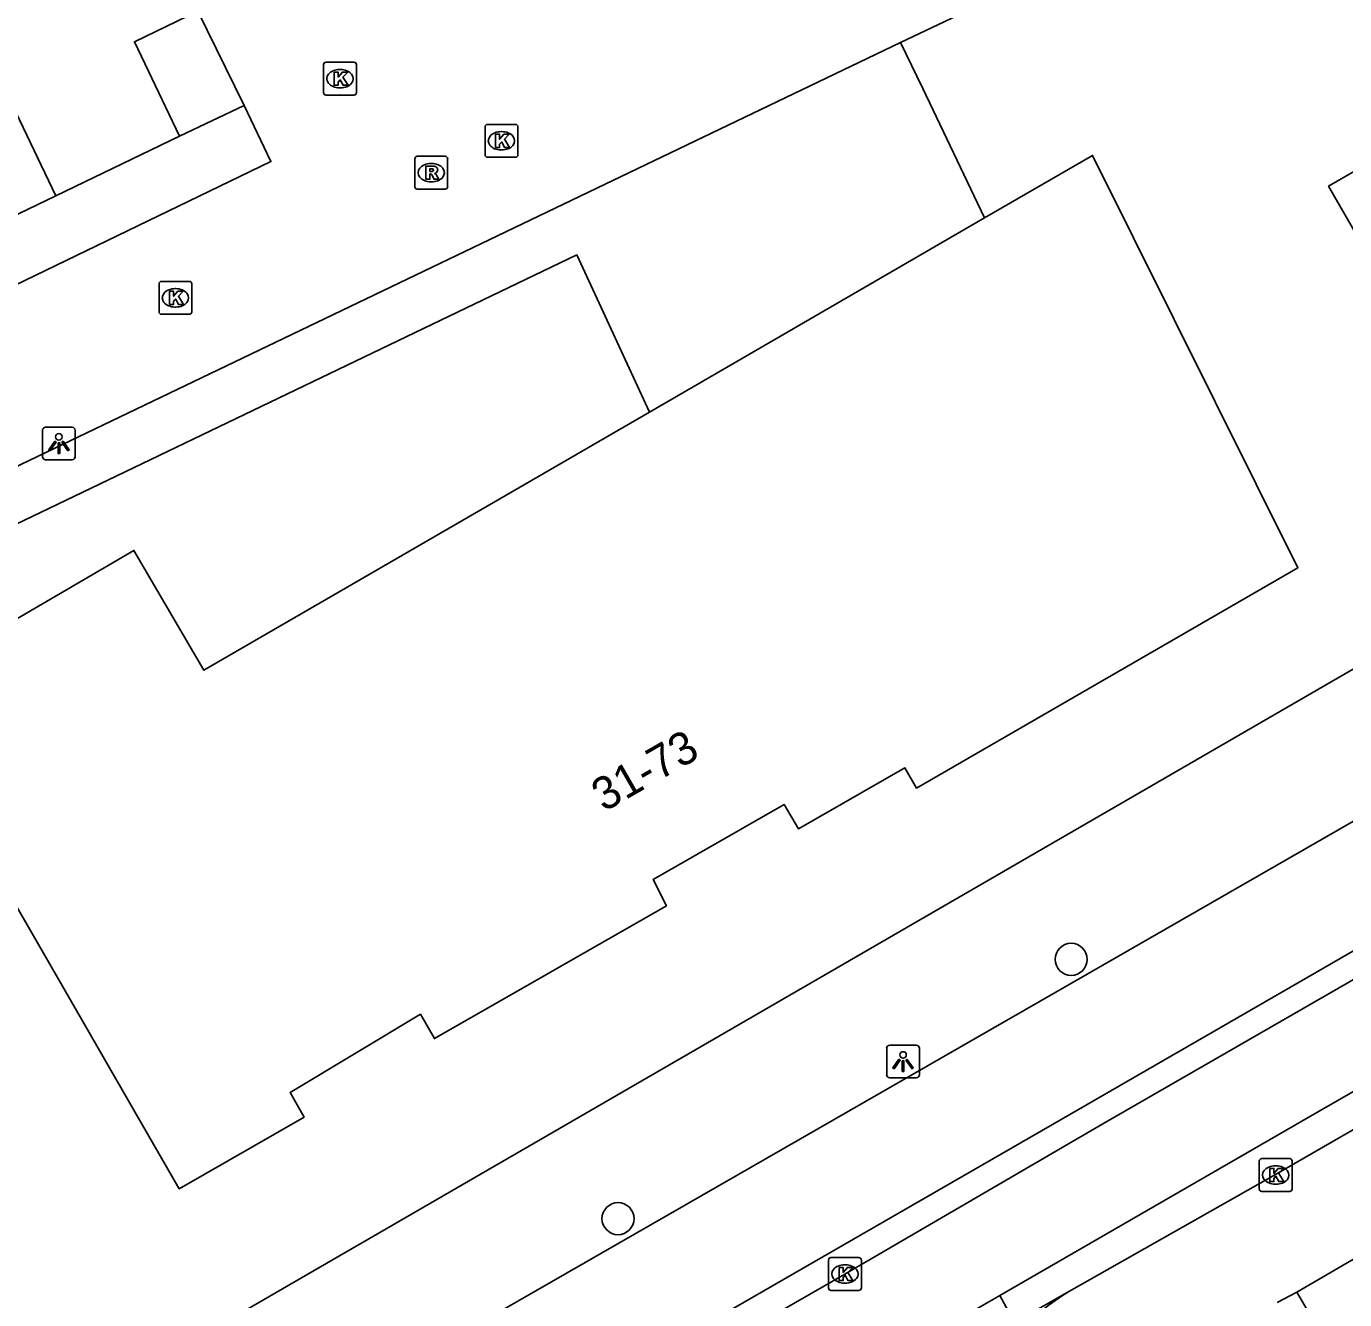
# Model space of a CAD drawing. Extents: x 158352 to 159489, y 383828 to 384597.
# Drawn here: x 159132.68 to 159172.84, y 383975.15 to 384013.95 of the extents above; entities that cross this region are included whole.
import ezdxf

# ---------------------------------------------------------------- set-up
doc = ezdxf.new("R2010")
doc.units = 0
for name, color, linetype in [('IMGEO_Boom', 7, 'Continuous'), ('IMGEO_Fietspad_gesloten', 7, 'Continuous'), ('IMGEO_Haag', 7, 'Continuous'), ('IMGEO_Kolk', 7, 'Continuous'), ('IMGEO_Lichtpunt', 7, 'Continuous'), ('IMGEO_Muur', 7, 'Continuous'), ('IMGEO_Pand', 7, 'Continuous'), ('IMGEO_Pand_nummerreeks', 7, 'Continuous'), ('IMGEO_Rijbaan_lokaal_open', 7, 'Continuous'), ('IMGEO_Rioolput', 7, 'Continuous'), ('IMGEO_Voetpad_open', 7, 'Continuous')]:
    doc.layers.add(name, color=color, linetype=linetype)

msp = doc.modelspace()

# ---------------------------------------------------------------- linework, layer by layer
at = {"layer": 'IMGEO_Boom'}
for centre in [(159164.512, 383985.52), (159150.704, 383977.62)]:
    msp.add_circle(centre, 0.489, dxfattribs=at)
at = {"layer": 'IMGEO_Fietspad_gesloten'}
for points in [[(159135.007, 383967.844), (159157.291, 383980.642), (159178.438, 383992.79)], [(159183.59, 383991.819), (159163.947, 383980.489), (159139.352, 383966.321)]]:
    msp.add_lwpolyline(points, dxfattribs=at)
at = {"layer": 'IMGEO_Haag'}
msp.add_lwpolyline([(159164.461, 383975.412), (159162.787, 383974.459), (159162.338, 383975.274)], dxfattribs=at)
at = {"layer": 'IMGEO_Kolk'}
for p, q in [((159141.732, 384011.926), (159141.732, 384012.778)), ((159141.807, 384012.852), (159142.659, 384012.852)), ((159142.22, 384012.632), (159142.245, 384012.632)), ((159142.733, 384012.778), (159142.733, 384011.926)), ((159142.659, 384011.852), (159141.807, 384011.852)), ((159142.243, 384012.072), (159142.218, 384012.072)), ((159146.652, 384010.034), (159146.652, 384010.886)), ((159146.727, 384010.96), (159147.579, 384010.96)), ((159147.653, 384010.886), (159147.653, 384010.034)), ((159147.14, 384010.74), (159147.165, 384010.74)), ((159147.163, 384010.18), (159147.138, 384010.18)), ((159147.579, 384009.96), (159146.727, 384009.96)), ((159136.718, 384005.249), (159136.718, 384006.101)), ((159136.793, 384006.175), (159137.645, 384006.175)), ((159137.719, 384006.101), (159137.719, 384005.249)), ((159137.206, 384005.955), (159137.231, 384005.955)), ((159137.229, 384005.395), (159137.204, 384005.395)), ((159137.645, 384005.175), (159136.793, 384005.175)), ((159170.243, 383978.523), (159170.243, 383979.375)), ((159170.318, 383979.449), (159171.17, 383979.449)), ((159170.731, 383979.229), (159170.756, 383979.229)), ((159171.244, 383979.375), (159171.244, 383978.523)), ((159171.17, 383978.449), (159170.318, 383978.449)), ((159170.754, 383978.669), (159170.729, 383978.669)), ((159157.118, 383975.508), (159157.118, 383976.36)), ((159157.193, 383976.434), (159158.045, 383976.434)), ((159158.119, 383976.36), (159158.119, 383975.508)), ((159157.606, 383976.214), (159157.631, 383976.214)), ((159157.629, 383975.654), (159157.604, 383975.654)), ((159158.045, 383975.434), (159157.193, 383975.434))]:
    msp.add_line(p, q, dxfattribs=at)
for points in [[(159141.732, 384011.926), (159141.732, 384012.778)], [(159141.807, 384012.852), (159142.659, 384012.852)], [(159142.053, 384012.552), (159142.176, 384012.552), (159142.176, 384012.401), (159142.306, 384012.552), (159142.47, 384012.552), (159142.324, 384012.401), (159142.477, 384012.152), (159142.325, 384012.152), (159142.24, 384012.316), (159142.176, 384012.249), (159142.176, 384012.152), (159142.053, 384012.152), (159142.053, 384012.552)], [(159142.733, 384012.778), (159142.733, 384011.926)], [(159142.659, 384011.852), (159141.807, 384011.852)], [(159146.652, 384010.034), (159146.652, 384010.886)], [(159146.727, 384010.96), (159147.579, 384010.96)], [(159147.653, 384010.886), (159147.653, 384010.034)], [(159146.973, 384010.66), (159147.096, 384010.66), (159147.096, 384010.509), (159147.226, 384010.66), (159147.39, 384010.66), (159147.244, 384010.509), (159147.397, 384010.26), (159147.245, 384010.26), (159147.16, 384010.424), (159147.096, 384010.357), (159147.096, 384010.26), (159146.973, 384010.26), (159146.973, 384010.66)], [(159147.579, 384009.96), (159146.727, 384009.96)], [(159136.718, 384005.249), (159136.718, 384006.101)], [(159136.793, 384006.175), (159137.645, 384006.175)], [(159137.719, 384006.101), (159137.719, 384005.249)], [(159137.039, 384005.875), (159137.162, 384005.875), (159137.162, 384005.724), (159137.292, 384005.875), (159137.456, 384005.875), (159137.31, 384005.724), (159137.463, 384005.475), (159137.311, 384005.475), (159137.226, 384005.639), (159137.162, 384005.572), (159137.162, 384005.475), (159137.039, 384005.475), (159137.039, 384005.875)], [(159137.645, 384005.175), (159136.793, 384005.175)], [(159170.243, 383978.523), (159170.243, 383979.375)], [(159170.318, 383979.449), (159171.17, 383979.449)], [(159171.244, 383979.375), (159171.244, 383978.523)], [(159170.564, 383979.149), (159170.687, 383979.149), (159170.687, 383978.998), (159170.817, 383979.149), (159170.981, 383979.149), (159170.835, 383978.998), (159170.988, 383978.749), (159170.836, 383978.749), (159170.751, 383978.913), (159170.687, 383978.846), (159170.687, 383978.749), (159170.564, 383978.749), (159170.564, 383979.149)], [(159171.17, 383978.449), (159170.318, 383978.449)], [(159157.118, 383975.508), (159157.118, 383976.36)], [(159157.193, 383976.434), (159158.045, 383976.434)], [(159158.119, 383976.36), (159158.119, 383975.508)], [(159157.439, 383976.134), (159157.562, 383976.134), (159157.562, 383975.983), (159157.692, 383976.134), (159157.856, 383976.134), (159157.71, 383975.983), (159157.863, 383975.734), (159157.711, 383975.734), (159157.626, 383975.898), (159157.562, 383975.831), (159157.562, 383975.734), (159157.439, 383975.734), (159157.439, 383976.134)], [(159158.045, 383975.434), (159157.193, 383975.434)]]:
    msp.add_lwpolyline(points, dxfattribs=at)
for centre, start, end in [((159141.809, 384012.776), 91.552, 178.448), ((159141.809, 384012.776), 91.552, 178.448), ((159142.657, 384012.776), 1.552, 88.448), ((159142.657, 384012.776), 1.552, 88.448), ((159141.809, 384011.928), 181.552, 268.448), ((159141.809, 384011.928), 181.552, 268.448), ((159142.657, 384011.928), 271.552, 358.448), ((159142.657, 384011.928), 271.552, 358.448), ((159146.729, 384010.884), 91.552, 178.448), ((159146.729, 384010.884), 91.552, 178.448), ((159147.577, 384010.884), 1.552, 88.448), ((159147.577, 384010.884), 1.552, 88.448), ((159146.729, 384010.036), 181.552, 268.448), ((159146.729, 384010.036), 181.552, 268.448), ((159147.577, 384010.036), 271.552, 358.448), ((159147.577, 384010.036), 271.552, 358.448), ((159136.795, 384006.099), 91.552, 178.448), ((159136.795, 384006.099), 91.552, 178.448), ((159137.643, 384006.099), 1.552, 88.448), ((159137.643, 384006.099), 1.552, 88.448), ((159136.795, 384005.251), 181.552, 268.448), ((159136.795, 384005.251), 181.552, 268.448), ((159137.643, 384005.251), 271.552, 358.448), ((159137.643, 384005.251), 271.552, 358.448), ((159170.32, 383979.373), 91.552, 178.448), ((159170.32, 383979.373), 91.552, 178.448), ((159171.168, 383979.373), 1.552, 88.448), ((159171.168, 383979.373), 1.552, 88.448), ((159170.32, 383978.525), 181.552, 268.448), ((159170.32, 383978.525), 181.552, 268.448), ((159171.168, 383978.525), 271.552, 358.448), ((159171.168, 383978.525), 271.552, 358.448), ((159157.195, 383976.358), 91.552, 178.448), ((159157.195, 383976.358), 91.552, 178.448), ((159158.043, 383976.358), 1.552, 88.448), ((159158.043, 383976.358), 1.552, 88.448), ((159157.195, 383975.51), 181.552, 268.448), ((159157.195, 383975.51), 181.552, 268.448), ((159158.043, 383975.51), 271.552, 358.448), ((159158.043, 383975.51), 271.552, 358.448)]:
    msp.add_arc(centre, 0.0765, start, end, dxfattribs=at)
for centre, major_axis, ratio, start_param, end_param in [((159142.219, 384012.352), (-0.387, 0.002), 0.722429, 4.712389, 7.853982), ((159142.244, 384012.352), (-0.39, 0.002), 0.717154, 1.570796, 4.712389), ((159147.139, 384010.46), (-0.387, 0.002), 0.722429, 4.712389, 7.853982), ((159147.164, 384010.46), (-0.39, 0.002), 0.717154, 1.570796, 4.712389), ((159137.205, 384005.675), (-0.387, 0.002), 0.722429, 4.712389, 7.853982), ((159137.23, 384005.675), (-0.39, 0.002), 0.717154, 1.570796, 4.712389), ((159170.73, 383978.949), (-0.387, 0.002), 0.722429, 4.712389, 7.853982), ((159170.755, 383978.949), (-0.39, 0.002), 0.717154, 1.570796, 4.712389), ((159157.605, 383975.934), (-0.387, 0.002), 0.722429, 4.712389, 7.853982), ((159157.63, 383975.934), (-0.39, 0.002), 0.717154, 1.570796, 4.712389)]:
    msp.add_ellipse(centre, major_axis=major_axis, ratio=ratio, start_param=start_param, end_param=end_param, dxfattribs=at)
at = {"layer": 'IMGEO_Lichtpunt'}
for p, q in [((159134.071, 384001.737), (159133.263, 384001.737)), ((159134.071, 384001.737), (159133.263, 384001.737)), ((159133.169, 384001.642), (159133.169, 384000.835)), ((159133.169, 384001.642), (159133.169, 384000.835)), ((159134.165, 384000.835), (159134.165, 384001.642)), ((159134.165, 384000.835), (159134.165, 384001.642)), ((159133.263, 384000.741), (159134.071, 384000.741)), ((159133.263, 384000.741), (159134.071, 384000.741)), ((159158.89, 383982.81), (159158.89, 383982.003)), ((159158.89, 383982.81), (159158.89, 383982.003)), ((159159.792, 383982.905), (159158.984, 383982.905)), ((159159.792, 383982.905), (159158.984, 383982.905)), ((159159.886, 383982.003), (159159.886, 383982.81)), ((159159.886, 383982.003), (159159.886, 383982.81)), ((159158.984, 383981.909), (159159.792, 383981.909)), ((159158.984, 383981.909), (159159.792, 383981.909))]:
    msp.add_line(p, q, dxfattribs=at)
for points in [[(159133.543, 384001.306), (159133.582, 384001.278), (159133.394, 384001.016), (159133.356, 384001.043), (159133.543, 384001.306)], [(159133.645, 384001.258), (159133.692, 384001.258), (159133.692, 384000.936), (159133.645, 384000.936), (159133.645, 384001.258)], [(159133.755, 384001.278), (159133.793, 384001.305), (159133.98, 384001.043), (159133.941, 384001.015), (159133.755, 384001.278)], [(159159.264, 383982.474), (159159.303, 383982.446), (159159.115, 383982.184), (159159.077, 383982.211), (159159.264, 383982.474)], [(159159.366, 383982.426), (159159.413, 383982.426), (159159.413, 383982.104), (159159.366, 383982.104), (159159.366, 383982.426)], [(159159.476, 383982.446), (159159.514, 383982.473), (159159.701, 383982.211), (159159.662, 383982.183), (159159.476, 383982.446)]]:
    msp.add_lwpolyline(points, dxfattribs=at)
for centre in [(159133.668, 384001.44), (159159.389, 383982.608)]:
    msp.add_circle(centre, 0.0994, dxfattribs=at)
for centre, start, end in [((159133.263, 384001.642), 90, 180), ((159133.263, 384001.642), 90, 180), ((159134.071, 384001.642), 0, 90), ((159134.071, 384001.642), 0, 90), ((159133.263, 384000.835), 180, 270), ((159133.263, 384000.835), 180, 270), ((159134.071, 384000.835), 270, 0), ((159134.071, 384000.835), 270, 360), ((159158.984, 383982.81), 90, 180), ((159158.984, 383982.81), 90, 180), ((159159.792, 383982.81), 0, 90), ((159159.792, 383982.81), 0, 90), ((159158.984, 383982.003), 180, 270), ((159158.984, 383982.003), 180, 270), ((159159.792, 383982.003), 270, 0), ((159159.792, 383982.003), 270, 360)]:
    msp.add_arc(centre, 0.0946, start, end, dxfattribs=at)
at = {"layer": 'IMGEO_Muur'}
msp.add_lwpolyline([(159133.572, 384008.786), (159137.345, 384010.601)], dxfattribs=at)
at = {"layer": 'IMGEO_Pand'}
for points in [[(159210.155, 384016.874), (159180.797, 384000), (159178.382, 383998.612), (159177.583, 384000), (159172.356, 384009.08), (159176.703, 384011.583), (159197.634, 384023.633), (159196.913, 384024.885), (159199.089, 384031.944), (159200.516, 384032.566), (159191.751, 384052.673), (159198.299, 384055.527), (159201.06, 384056.748)], [(159137.345, 384010.601), (159135.97, 384013.478), (159137.906, 384014.412)], [(159137.906, 384014.412), (159139.312, 384011.539)], [(159131.122, 384013.88), (159133.572, 384008.786)], [(159139.312, 384011.539), (159137.345, 384010.601)], [(159161.874, 384008.109), (159165.164, 384010.014), (159170.145, 384000), (159171.416, 383997.444), (159159.798, 383990.739), (159159.444, 383991.354), (159156.203, 383989.498), (159155.771, 383990.237), (159151.773, 383987.95), (159152.178, 383987.153), (159145.111, 383983.105), (159144.681, 383983.848), (159140.714, 383981.459), (159141.14, 383980.715), (159137.336, 383978.532), (159131.683, 383988.314)], [(159123.436, 384003.94), (159130.74, 384007.424), (159133.572, 384008.786)], [(159151.664, 384002.195), (159161.874, 384008.109)], [(159128.32, 383993.529), (159135.953, 383997.977), (159138.083, 383994.328), (159147.875, 384000), (159151.664, 384002.195)], [(159181.483, 383981.264), (159184.516, 383976.063), (159184.009, 383975.768), (159179.668, 383973.237), (159173.995, 383970.914), (159171.391, 383975.38)], [(159171.391, 383975.38), (159181.483, 383981.264)]]:
    msp.add_lwpolyline(points, dxfattribs=at)
at = {"layer": 'IMGEO_Rijbaan_lokaal_open'}
for points in [[(159155.289, 384035.597), (159162.921, 384021.106), (159165.143, 384016.224), (159159.311, 384013.456)], [(159159.311, 384013.456), (159131.25, 384000), (159121.98, 383995.555)], [(159139.312, 384011.539), (159140.13, 384009.826), (159119.833, 384000.022)], [(159179.1, 383988.347), (159165.477, 383980.512), (159157.62, 383975.933), (159140.266, 383965.967), (159140.072, 383965.861)], [(159162.338, 383975.274), (159172.065, 383980.896), (159183.324, 383987.357)], [(159183.788, 383986.558), (159174.791, 383981.305), (159170.733, 383978.963), (159164.461, 383975.412)], [(159162.338, 383975.274), (159136.64, 383960.422), (159125.435, 383954.227)], [(159170.793, 383975.067), (159171.391, 383975.38)]]:
    msp.add_lwpolyline(points, dxfattribs=at)
msp.add_arc((159168.476, 383968.802), 7.734, 121.2715, 150.611, dxfattribs=at)
at = {"layer": 'IMGEO_Rioolput'}
for p, q in [((159144.512, 384009.061), (159144.512, 384009.913)), ((159144.587, 384009.987), (159145.439, 384009.987)), ((159145, 384009.767), (159145.025, 384009.767)), ((159145.513, 384009.913), (159145.513, 384009.061)), ((159145.439, 384008.987), (159144.587, 384008.987)), ((159145.023, 384009.207), (159144.998, 384009.207))]:
    msp.add_line(p, q, dxfattribs=at)
for points in [[(159144.512, 384009.061), (159144.512, 384009.913)], [(159144.587, 384009.987), (159145.439, 384009.987)], [(159145.101, 384009.685), (159144.849, 384009.687), (159144.849, 384009.287)], [(159145.513, 384009.913), (159145.513, 384009.061)], [(159144.849, 384009.287), (159144.973, 384009.287), (159144.973, 384009.449), (159144.984, 384009.449)], [(159145.027, 384009.606), (159144.973, 384009.606), (159144.973, 384009.525)], [(159144.973, 384009.525), (159145.025, 384009.525)], [(159145.031, 384009.42), (159145.102, 384009.287), (159145.242, 384009.287), (159145.177, 384009.413)], [(159145.439, 384008.987), (159144.587, 384008.987)]]:
    msp.add_lwpolyline(points, dxfattribs=at)
for centre, radius, start, end in [((159144.589, 384009.911), 0.0765, 91.552, 178.448), ((159144.589, 384009.911), 0.0765, 91.552, 178.448), ((159145.1, 384009.575), 0.109, 350.3612, 89.416), ((159145.437, 384009.911), 0.0765, 1.552, 88.448), ((159145.437, 384009.911), 0.0765, 1.552, 88.448), ((159144.983, 384009.396), 0.0533, 26.0293, 88.6989), ((159145.009, 384009.714), 0.19, 274.7715, 282.9687), ((159145.033, 384009.51), 0.0964, 77.0061, 93.1865), ((159145.047, 384009.567), 0.0378, 276.6634, 79.6772), ((159145.098, 384009.575), 0.112, 277.5842, 350.9817), ((159145.082, 384009.36), 0.108, 29.5134, 73.7905), ((159144.589, 384009.063), 0.0765, 181.552, 268.448), ((159144.589, 384009.063), 0.0765, 181.552, 268.448), ((159145.437, 384009.063), 0.0765, 271.552, 358.448), ((159145.437, 384009.063), 0.0765, 271.552, 358.448)]:
    msp.add_arc(centre, radius, start, end, dxfattribs=at)
for centre, major_axis, ratio, start_param, end_param in [((159144.999, 384009.487), (-0.387, 0.002), 0.722429, 4.712389, 7.853982), ((159145.024, 384009.487), (-0.39, 0.002), 0.717154, 1.570796, 4.712389)]:
    msp.add_ellipse(centre, major_axis=major_axis, ratio=ratio, start_param=start_param, end_param=end_param, dxfattribs=at)
at = {"layer": 'IMGEO_Voetpad_open'}
for points in [[(159159.311, 384013.456), (159159.995, 384012.05), (159161.874, 384008.109)], [(159133.572, 384008.786), (159137.345, 384010.601)], [(159151.664, 384002.195), (159149.447, 384006.984), (159134.907, 384000), (159122.671, 383994.123)], [(159135.972, 383972.875), (159176.746, 383996.469)]]:
    msp.add_lwpolyline(points, dxfattribs=at)

# ---------------------------------------------------------------- texts
at = {"layer": 'IMGEO_Pand_nummerreeks'}
msp.add_text('31-73', height=1, rotation=29.7711, dxfattribs=at).set_placement((159150.277, 383989.998))

doc.saveas('drawing.dxf')
